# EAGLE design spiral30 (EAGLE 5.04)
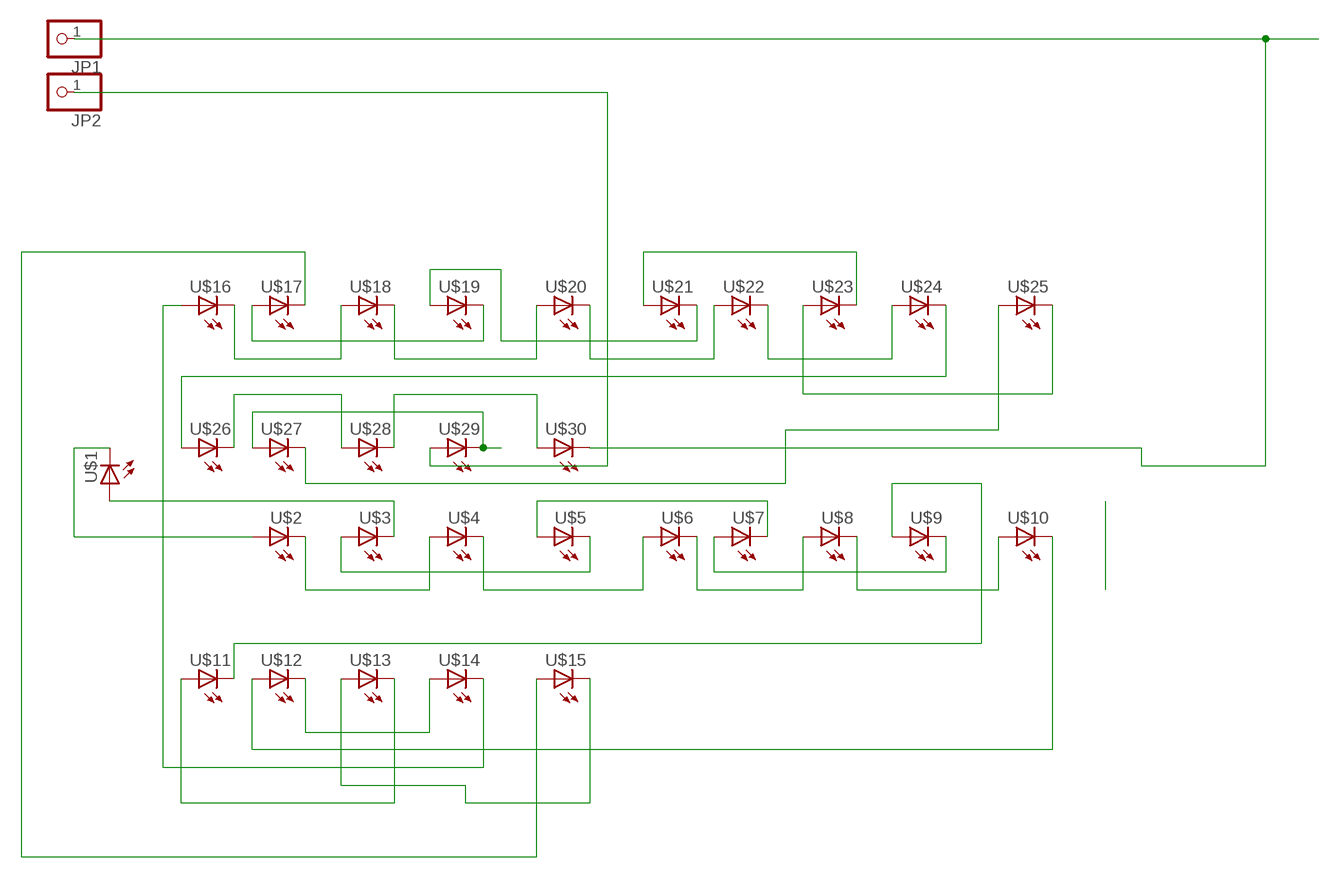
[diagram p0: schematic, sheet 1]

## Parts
JP1  PINHD-1X1  [1X01]
JP2  PINHD-1X1  [1X01]
U$1  LED5MM  [LED5MM]
U$2  LED5MM  [LED5MM]
U$3  LED5MM  [LED5MM]
U$4  LED5MM  [LED5MM]
U$5  LED5MM  [LED5MM]
U$6  LED5MM  [LED5MM]
U$7  LED5MM  [LED5MM]
U$8  LED5MM  [LED5MM]
U$9  LED5MM  [LED5MM]
U$10  LED5MM  [LED5MM]
U$11  LED5MM  [LED5MM]
U$12  LED5MM  [LED5MM]
U$13  LED5MM  [LED5MM]
U$14  LED5MM  [LED5MM]
U$15  LED5MM  [LED5MM]
U$16  LED5MM  [LED5MM]
U$17  LED5MM  [LED5MM]
U$18  LED5MM  [LED5MM]
U$19  LED5MM  [LED5MM]
U$20  LED5MM  [LED5MM]
U$21  LED5MM  [LED5MM]
U$22  LED5MM  [LED5MM]
U$23  LED5MM  [LED5MM]
U$24  LED5MM  [LED5MM]
U$25  LED5MM  [LED5MM]
U$26  LED5MM  [LED5MM]
U$27  LED5MM  [LED5MM]
U$28  LED5MM  [LED5MM]
U$29  LED5MM  [LED5MM]
U$30  LED5MM  [LED5MM]

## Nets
N$1: JP1.1 U$30.K(C)
N$2: U$2.K(C) U$4.A
N$3: U$4.K(C) U$6.A
N$4: U$6.K(C) U$8.A
N$5: U$8.K(C) U$10.A
N$6: U$1.A U$3.K(C)
N$7: U$3.A U$5.K(C)
N$8: U$5.A U$7.K(C)
N$9: U$7.A U$9.K(C)
N$10: U$10.K(C) U$12.A
N$11: U$12.K(C) U$14.A
N$12: U$14.K(C) U$16.A
N$13: U$16.K(C) U$18.A
N$14: U$18.K(C) U$20.A
N$15: U$20.K(C) U$22.A
N$16: U$22.K(C) U$24.A
N$17: U$24.K(C) U$26.A
N$18: U$26.K(C) U$28.A
N$19: U$28.K(C) U$30.A
N$22: U$1.K(C) U$2.A
N$23: U$27.A U$29.K(C)
N$24: U$25.A U$27.K(C)
N$27: U$9.A U$11.K(C)
N$29: U$11.A U$13.K(C)
N$30: U$13.A U$15.K(C)
N$31: U$15.A U$17.K(C)
N$32: U$17.A U$19.K(C)
N$33: U$19.A U$21.K(C)
N$34: U$21.A U$23.K(C)
N$35: U$23.A U$25.K(C)
V300: JP2.1 U$29.A

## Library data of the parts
JP1 JP2 = pinhead:PINHD-1X1: PIN HEADER
U$1-U$30 = led(2):LED: LED

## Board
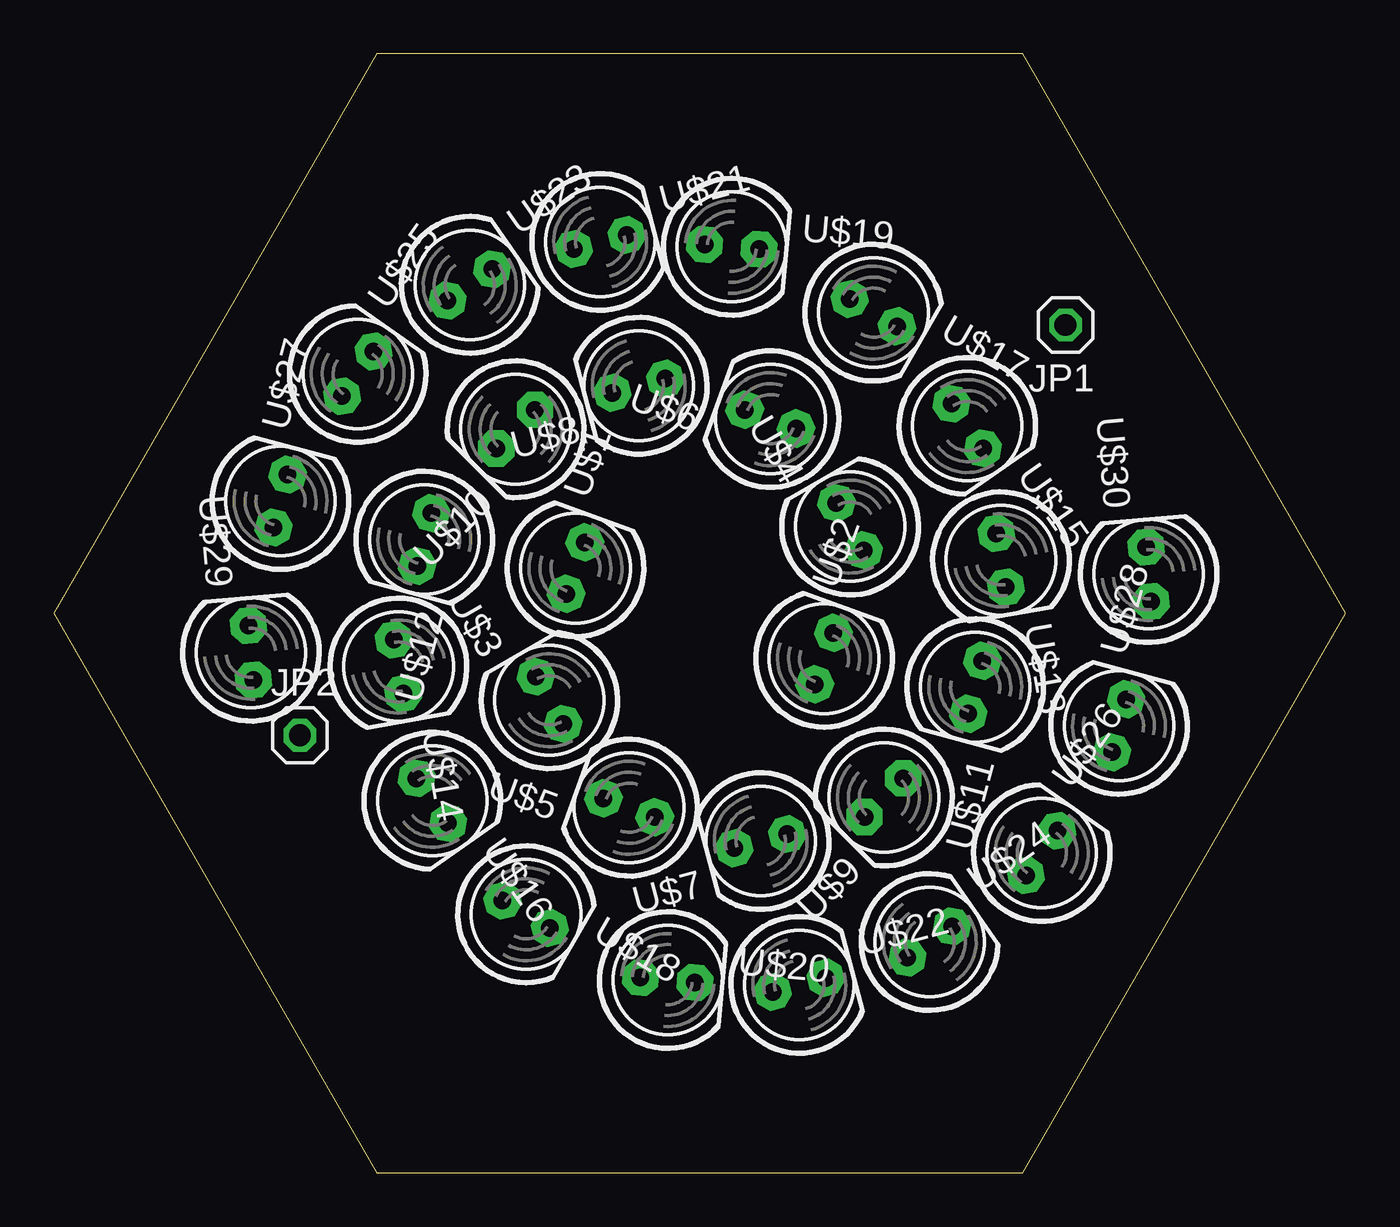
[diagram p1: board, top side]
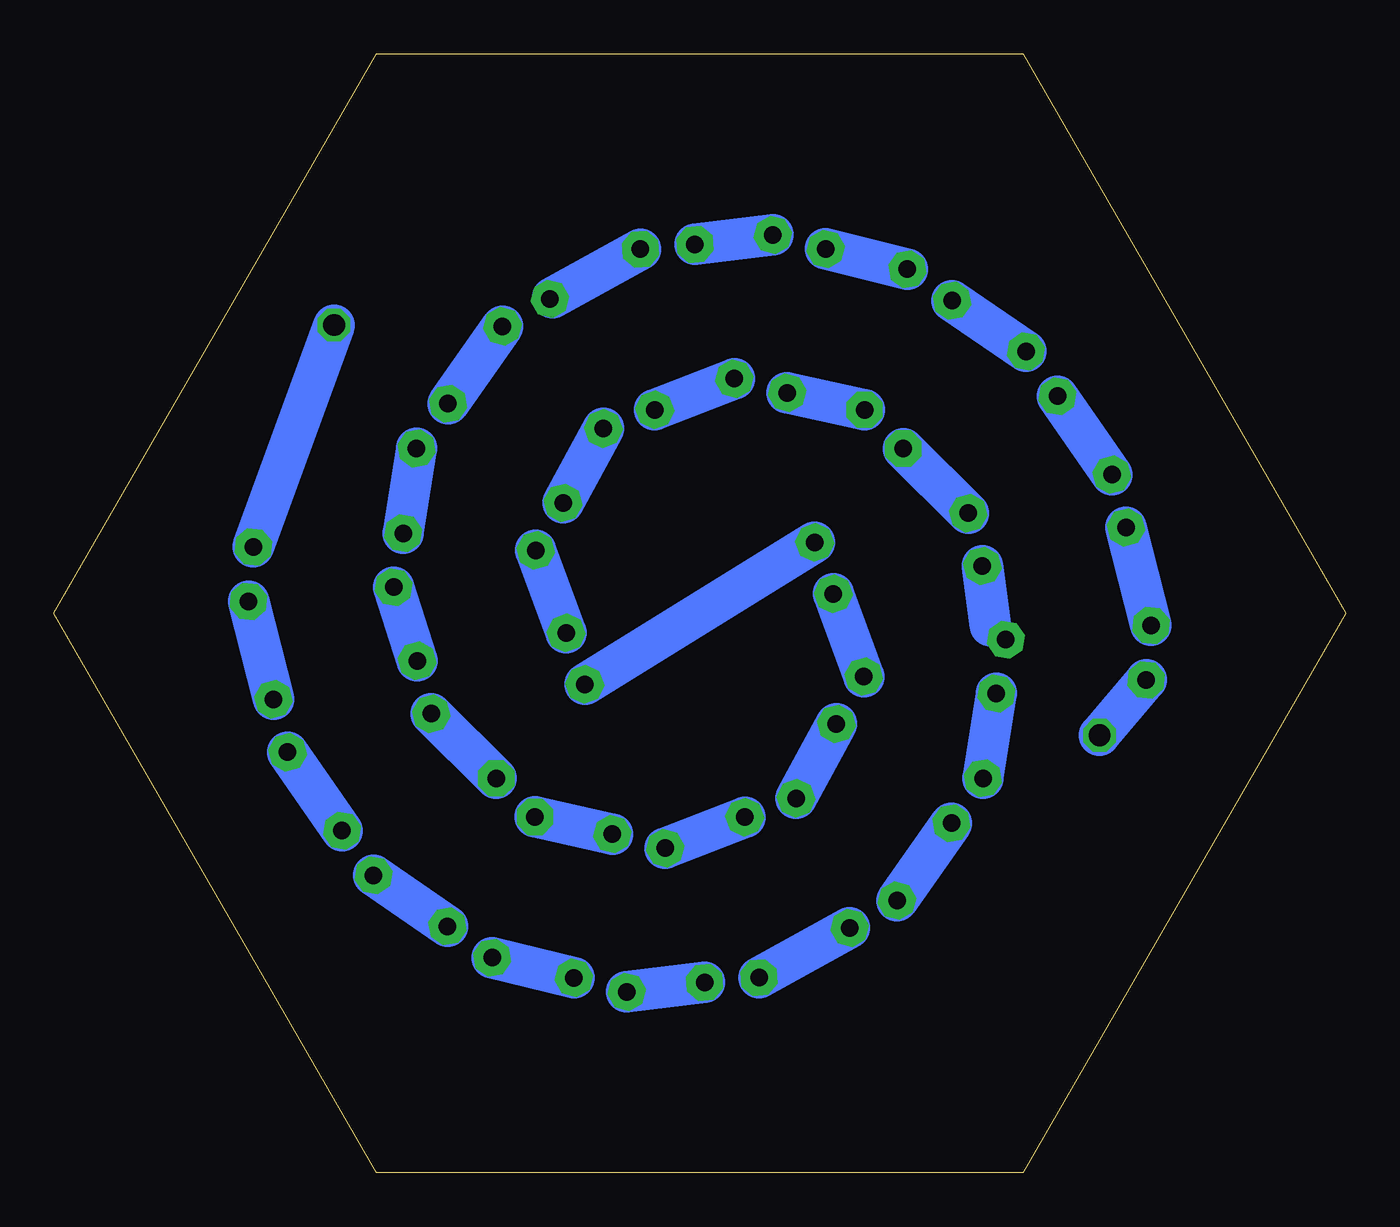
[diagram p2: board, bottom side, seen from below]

Size 60 x 51.96 mm. Coordinates in mm from the lower left corner, seen from the top.
Outline: 15,0 45,0 60,25.98 45,51.96 15,51.96 0,25.98 15,0
Copper layers (1*16): Top 0.035mm / dielectric 1.5mm / Bottom 0.035mm
Design rules "default": minimum track width 10mil, minimum drill 24mil, track to track 8mil, track to pad 8mil, pad to pad 8mil, via to via 8mil, smd to smd 8mil, copper to edge 40mil, drill to drill 8mil, minimum pad ring 10mil, minimum via ring 8mil, stop-mask expansion 4mil, vias tented up to drill 0mil, thermal gap 10mil

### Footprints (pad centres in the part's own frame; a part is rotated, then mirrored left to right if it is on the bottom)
1X01 = drill 1.016 octagon: 1 0,0
LED5MM = drill 0.813 pad 1.676 octagon: A -1.27,0; K 1.27,0

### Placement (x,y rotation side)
JP1  46.99,39.37 180 top
JP2  11.43,20.32 0 top
U$1  24.23,28.08 70 top
U$2  35.77,23.88 70 top
U$3  23.02,21.95 120 top
U$4  36.98,30.01 120 top
U$5  26.72,16.96 160 top
U$6  33.28,35 160 top
U$7  32.83,15.41 195 top
U$8  27.17,36.55 195 top
U$9  38.55,17.43 225 top
U$10  21.45,34.53 225 top
U$11  42.8,22.55 255 top
U$12  17.2,29.41 255 top
U$13  43.99,28.45 280 top
U$14  16.01,23.51 280 top
U$15  42.42,34.68 305 top
U$16  17.58,17.28 305 top
U$17  38.06,39.95 330 top
U$18  21.94,12.01 330 top
U$19  31.49,43 355 top
U$20  28.51,8.96 355 top
U$21  25.38,43.23 14.9 top
U$22  34.62,8.73 14.9 top
U$23  19.32,41.23 35 top
U$24  40.68,10.73 35 top
U$25  14.12,37.1 54.9 top
U$26  45.88,14.86 54.9 top
U$27  10.53,31.2 75 top
U$28  49.47,20.76 75 top
U$29  9.15,24.16 95 top
U$30  50.85,27.8 95 top

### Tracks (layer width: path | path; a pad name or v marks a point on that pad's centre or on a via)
N$1
  Bottom 1.93: U$30.K JP1.1
N$2
  Bottom 1.93: U$2.K U$4.A
N$3
  Bottom 1.93: U$4.K U$6.A
N$4
  Bottom 1.93: U$6.K U$8.A
N$5
  Bottom 1.93: U$8.K U$10.A
N$6
  Bottom 1.93: U$3.K U$1.A
N$7
  Bottom 1.93: U$5.K U$3.A
N$8
  Bottom 1.93: U$7.K U$5.A
N$9
  Bottom 1.93: U$9.K U$7.A
N$10
  Bottom 1.93: U$10.K U$12.A
N$11
  Bottom 1.016: 16.51,25.4 U$14.A
  Bottom 1.93: U$12.K 16.51,25.4
N$12
  Bottom 1.93: U$14.K U$16.A
N$13
  Bottom 1.93: U$16.K U$18.A
N$14
  Bottom 1.93: U$18.K U$20.A
N$15
  Bottom 1.93: U$20.K U$22.A
N$16
  Bottom 1.93: U$22.K U$24.A
N$17
  Bottom 1.93: U$24.K U$26.A
N$18
  Bottom 1.93: U$26.K U$28.A
N$19
  Bottom 1.93: U$28.K U$30.A
N$22
  Bottom 1.93: U$1.K U$2.A
N$23
  Bottom 1.93: U$29.K U$27.A
N$24
  Bottom 1.93: U$27.K U$25.A
N$27
  Bottom 1.93: U$11.K U$9.A
N$29
  Bottom 1.93: U$13.K U$11.A
N$30
  Bottom 1.93: U$15.K U$13.A
N$31
  Bottom 1.93: U$17.K U$15.A
N$32
  Bottom 1.016: 36.83,40.64 U$17.A
  Bottom 1.93: U$19.K 36.83,40.64
N$33
  Bottom 1.93: U$21.K U$19.A
N$34
  Bottom 1.93: U$23.K U$21.A
N$35
  Bottom 1.93: U$25.K U$23.A
V300
  Bottom 1.93: U$29.A JP2.1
